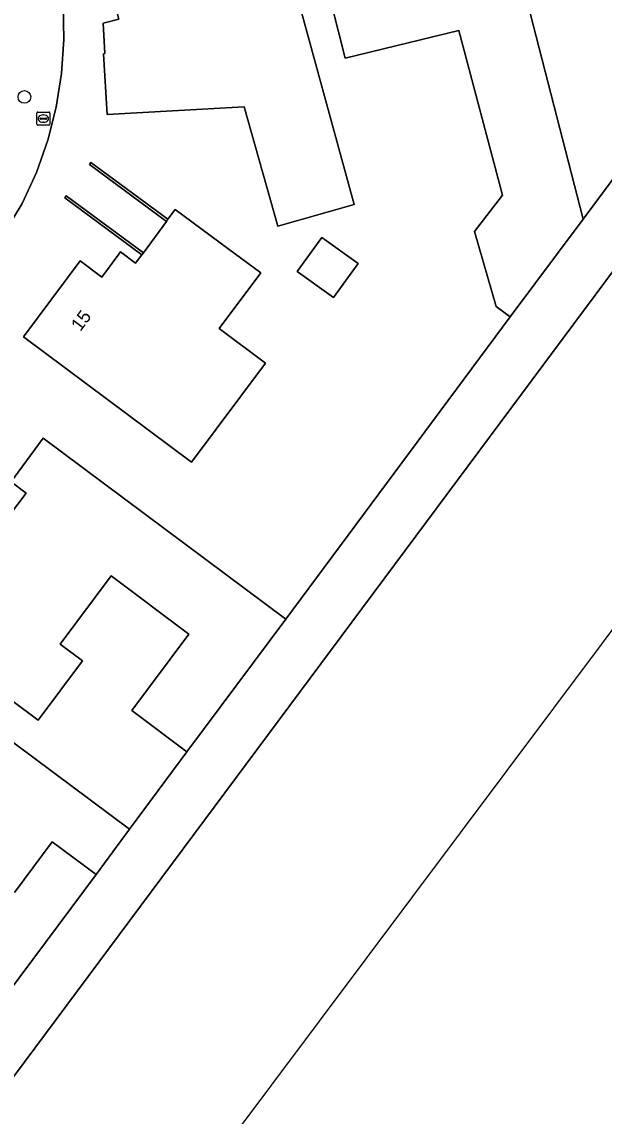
# Model space of a CAD drawing. Extents: x 158835 to 160077, y 386387 to 387778.
# Drawn here: x 159520.8 to 159565.2, y 386635.5 to 386719 of the extents above; entities that cross this region are included whole.
import ezdxf

# ---------------------------------------------------------------- set-up
doc = ezdxf.new("R2010")
doc.units = 0
for name, color, linetype in [('IMGEO_Boom', 7, 'Continuous'), ('IMGEO_Brandkraan', 7, 'Continuous'), ('IMGEO_Erf', 7, 'Continuous'), ('IMGEO_Grasland_agrarisch', 7, 'Continuous'), ('IMGEO_Groenvoorziening', 7, 'Continuous'), ('IMGEO_Muur', 7, 'Continuous'), ('IMGEO_Pand', 7, 'Continuous'), ('IMGEO_Pand_nummerreeks', 7, 'Continuous'), ('IMGEO_Voetpad_open', 7, 'Continuous')]:
    doc.layers.add(name, color=color, linetype=linetype)

msp = doc.modelspace()

# ---------------------------------------------------------------- linework, layer by layer
at = {"layer": 'IMGEO_Boom'}
msp.add_circle((159520.987, 386713.228), 0.489, dxfattribs=at)
at = {"layer": 'IMGEO_Brandkraan'}
for p, q in [((159521.933, 386711.149), (159521.933, 386712.001)), ((159522.008, 386712.075), (159522.86, 386712.075)), ((159522.192, 386711.569), (159522.192, 386711.581)), ((159522.63, 386711.532), (159522.232, 386711.532)), ((159522.235, 386711.618), (159522.633, 386711.618)), ((159522.444, 386711.295), (159522.419, 386711.295)), ((159522.421, 386711.855), (159522.446, 386711.855)), ((159522.676, 386711.581), (159522.676, 386711.569)), ((159522.934, 386712.001), (159522.934, 386711.149)), ((159522.86, 386711.075), (159522.008, 386711.075))]:
    msp.add_line(p, q, dxfattribs=at)
for points in [[(159521.933, 386711.149), (159521.933, 386712.001)], [(159522.008, 386712.075), (159522.86, 386712.075)], [(159522.934, 386712.001), (159522.934, 386711.149)], [(159522.86, 386711.075), (159522.008, 386711.075)]]:
    msp.add_lwpolyline(points, dxfattribs=at)
for centre, radius, start, end in [((159522.01, 386711.999), 0.0765, 91.55205, 178.44795), ((159522.01, 386711.999), 0.0765, 91.55205, 178.44795), ((159522.232, 386711.578), 0.0403, 85.87752, 175.75265), ((159522.229, 386711.568), 0.0366, 178.93798, 274.71019), ((159522.633, 386711.575), 0.043, 264.86636, 352.45326), ((159522.637, 386711.58), 0.0386, 1.73085, 96.63898), ((159522.858, 386711.999), 0.0765, 1.55205, 88.44795), ((159522.858, 386711.999), 0.0765, 1.55205, 88.44795), ((159522.01, 386711.151), 0.0765, 181.55205, 268.44795), ((159522.01, 386711.151), 0.0765, 181.55205, 268.44795), ((159522.858, 386711.151), 0.0765, 271.55205, 358.44795), ((159522.858, 386711.151), 0.0765, 271.55205, 358.44795)]:
    msp.add_arc(centre, radius, start, end, dxfattribs=at)
for centre, major_axis, ratio, start_param, end_param in [((159522.42, 386711.575), (-0.387, 0.002), 0.722429, 4.712389, 7.853982), ((159522.445, 386711.575), (-0.39, 0.002), 0.717154, 1.570796, 4.712389)]:
    msp.add_ellipse(centre, major_axis=major_axis, ratio=ratio, start_param=start_param, end_param=end_param, dxfattribs=at)
at = {"layer": 'IMGEO_Erf'}
for points in [[(159546.149, 386705.02), (159540.327, 386703.374), (159537.752, 386712.48), (159532.281, 386712.169), (159527.289, 386711.885), (159527.025, 386716.527), (159527.131, 386716.528), (159526.993, 386718.851), (159528.19, 386719.148), (159526.968, 386723.917), (159533.73, 386725.646), (159533.978, 386724.677), (159536.711, 386725.424), (159540.305, 386726.406), (159541.623, 386721.583)], [(159539.016, 386699.821), (159535.837, 386695.571), (159539.38, 386692.921), (159533.731, 386685.37), (159520.906, 386694.932), (159525.234, 386700.736), (159526.889, 386699.484), (159528.185, 386701.234), (159528.311, 386701.404), (159529.466, 386700.536), (159529.526, 386700.618), (159529.95, 386701.192), (159524.08, 386705.521), (159524.184, 386705.68), (159530.062, 386701.345), (159531.824, 386703.734), (159525.942, 386708.073), (159526.048, 386708.213), (159531.942, 386703.893), (159532.489, 386704.635), (159536.513, 386701.667)], [(159546.44, 386700.522), (159544.568, 386697.92), (159541.803, 386699.91), (159543.675, 386702.512)]]:
    msp.add_lwpolyline(points, close=True, dxfattribs=at)
for points in [[(159554.124, 386718.288), (159545.468, 386716.177), (159543.969, 386722.142), (159542.75, 386726.991), (159543.279, 386727.128)], [(159558.017, 386725.677), (159563.63, 386703.915), (159576.147, 386720.781)], [(159523.936, 386720.207), (159523.989, 386717.606), (159523.81, 386715.012), (159523.4, 386712.444), (159522.762, 386709.923), (159521.901, 386707.468), (159520.825, 386705.101), (159506.854, 386682.053), (159500.252, 386671.907), (159500, 386671.529), (159492.426, 386660.371), (159492.025, 386659.896), (159480.297, 386643.692), (159466.865, 386626.712)], [(159520.153, 386684.123), (159522.43, 386687.19), (159540.934, 386673.397), (159558.058, 386696.441), (159556.98, 386697.244), (159555.329, 386702.95), (159557.463, 386705.724), (159554.124, 386718.288)], [(159519.142, 386680.372), (159521.129, 386683.006), (159519.965, 386683.87)], [(159517.286, 386666.082), (159529.001, 386657.369), (159533.385, 386663.269), (159529.173, 386666.427), (159533.54, 386672.251), (159527.613, 386676.695), (159523.707, 386671.486), (159525.422, 386670.2), (159522.042, 386665.693), (159514.171, 386671.538)], [(159515.731, 386639.551), (159526.452, 386653.918), (159523.113, 386656.41), (159520.227, 386652.544)]]:
    msp.add_lwpolyline(points, dxfattribs=at)
at = {"layer": 'IMGEO_Grasland_agrarisch'}
for points in [[(159472.89, 386564.056), (159472.291, 386563.251), (159446.532, 386528.631), (159445.604, 386527.384), (159441.92, 386522.387), (159446.753, 386525.573), (159464.539, 386537.297), (159608.055, 386728.939), (159627.547, 386754.968)], [(159627.547, 386754.968), (159626.26, 386754.636), (159608.282, 386750), (159603.124, 386748.673), (159599.84, 386747.828), (159600.163, 386746.978), (159599.236, 386744.729), (159497.576, 386608.169), (159496.856, 386607.202), (159474.258, 386576.846)]]:
    msp.add_lwpolyline(points, dxfattribs=at)
at = {"layer": 'IMGEO_Groenvoorziening'}
msp.add_lwpolyline([(159599.236, 386744.729), (159600.163, 386746.978), (159599.84, 386747.828), (159595.413, 386746.689), (159591.302, 386741.165), (159576.147, 386720.781), (159563.63, 386703.915), (159558.058, 386696.441), (159540.934, 386673.397), (159533.385, 386663.269), (159529.001, 386657.369), (159526.452, 386653.918), (159515.731, 386639.551), (159510.292, 386632.116), (159505.124, 386625.269), (159502.142, 386621.255), (159495.593, 386611.141), (159497.576, 386608.169)], close=True, dxfattribs=at)
at = {"layer": 'IMGEO_Muur'}
for points in [[(159531.942, 386703.893), (159526.048, 386708.213), (159525.942, 386708.073), (159531.824, 386703.734)], [(159530.062, 386701.345), (159524.184, 386705.68), (159524.08, 386705.521), (159529.95, 386701.192)]]:
    msp.add_lwpolyline(points, close=True, dxfattribs=at)
at = {"layer": 'IMGEO_Pand'}
for points in [[(159543.279, 386727.128), (159542.75, 386726.991), (159543.969, 386722.142), (159545.468, 386716.177), (159554.124, 386718.288), (159557.463, 386705.724), (159555.329, 386702.95), (159556.98, 386697.244), (159558.058, 386696.441), (159563.63, 386703.915), (159558.017, 386725.677), (159556.798, 386730.526), (159551.353, 386729.157), (159551.512, 386728.516), (159548.757, 386727.815), (159548.605, 386728.457), (159548.085, 386728.335)], [(159520.227, 386652.544), (159523.113, 386656.41), (159526.452, 386653.918), (159529.001, 386657.369), (159517.286, 386666.082)]]:
    msp.add_lwpolyline(points, dxfattribs=at)
for points in [[(159526.968, 386723.917), (159528.19, 386719.148), (159526.993, 386718.851), (159527.131, 386716.528), (159527.025, 386716.527), (159527.289, 386711.885), (159532.281, 386712.169), (159537.752, 386712.48), (159540.327, 386703.374), (159546.149, 386705.02), (159541.623, 386721.583), (159540.305, 386726.406), (159536.711, 386725.424), (159533.978, 386724.677), (159533.73, 386725.646)], [(159520.906, 386694.932), (159533.731, 386685.37), (159539.38, 386692.921), (159535.837, 386695.571), (159539.016, 386699.821), (159536.513, 386701.667), (159532.489, 386704.635), (159531.942, 386703.893), (159531.824, 386703.734), (159530.062, 386701.345), (159529.95, 386701.192), (159529.526, 386700.618), (159529.466, 386700.536), (159528.311, 386701.404), (159528.185, 386701.234), (159526.889, 386699.484), (159525.234, 386700.736)], [(159541.803, 386699.91), (159544.568, 386697.92), (159546.44, 386700.522), (159543.675, 386702.512)], [(159522.43, 386687.19), (159520.153, 386684.123), (159519.965, 386683.87), (159521.129, 386683.006), (159519.142, 386680.372), (159517.176, 386681.83), (159513.533, 386676.904), (159515.461, 386675.464), (159516.506, 386674.684), (159514.171, 386671.538), (159522.042, 386665.693), (159525.422, 386670.2), (159523.707, 386671.486), (159527.613, 386676.695), (159533.54, 386672.251), (159529.173, 386666.427), (159533.385, 386663.269), (159540.934, 386673.397)]]:
    msp.add_lwpolyline(points, close=True, dxfattribs=at)
at = {"layer": 'IMGEO_Voetpad_open'}
msp.add_lwpolyline([(159452.919, 386610.024), (159466.865, 386626.712), (159480.297, 386643.692), (159492.025, 386659.896), (159492.426, 386660.371), (159500, 386671.529), (159500.252, 386671.907), (159506.854, 386682.053), (159520.825, 386705.101), (159521.901, 386707.468), (159522.762, 386709.923), (159523.4, 386712.444), (159523.81, 386715.012), (159523.989, 386717.606), (159523.936, 386720.207), (159523.829, 386721.437), (159523.607, 386726.844), (159524.846, 386728.532), (159523.605, 386733.299), (159523.378, 386733.241)], dxfattribs=at)

# ---------------------------------------------------------------- texts
at = {"layer": 'IMGEO_Pand_nummerreeks'}
msp.add_text('15', height=1, rotation=53.28838, dxfattribs=at).set_placement((159525.26, 386695.284))

doc.saveas('drawing.dxf')
